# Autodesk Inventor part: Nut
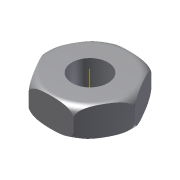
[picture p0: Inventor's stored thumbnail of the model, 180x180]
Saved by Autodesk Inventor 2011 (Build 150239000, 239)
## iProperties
Created: 2009-04
Part Number: Nut
Document SubType Name: Modeling
Designer: Sham
Density: 1 g/cm^3
Mass: 4.64221 g
Surface Area: 21.2945 cm^2
Volume: 4.64221 cm^3
Author: Sham
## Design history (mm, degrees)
sketch "Sketch1"
  geometry: L1 (7.5, 12.99)-(15, 0); L2 (15, 0)-(7.5, -12.99); L3 (7.5, -12.99)-(-7.5, -12.99); L4 (-7.5, -12.99)-(-15, 0); L5 (-15, 0)-(-7.5, 12.99); L6 (-7.5, 12.99)-(7.5, 12.99); C1 r 6 at (0, 0); 1 further point
  constraints: 12 end point, 1 centre point, 1 coincident, 13 other
  dimensions: "d0" = 30 distance of L1.end L4.end; "d1" = 12 diameter of C1
extrude "Extrusion1" new body sketch "Sketch1" distance "d2" = 12; taper "d3" = 0 deg
sketch "Sketch2"
  geometry: L1 (-12, 0)-(-12, -0.022); L2 (-15, 7)-(-15, 3); L3 (0, -2.87)-(0, 12.87) reference; A1 r 3 centre (-12, 7) between (-12, 10) and (-15, 7); A2 r 3 centre (-12, 3) between (-15, 3) and (-12, 0)
  constraints: 4 end point, 4 point on circle, 2 centre point, 1 tangent
revolve "Revolution1" sketch "Sketch2" stored, may be unused: angle "d7" = 90 deg
body "Solid1"
other parameters: "d6" = 90 deg
